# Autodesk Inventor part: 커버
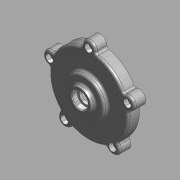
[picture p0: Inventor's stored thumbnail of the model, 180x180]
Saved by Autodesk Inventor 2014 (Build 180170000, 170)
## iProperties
Created: 2015-11
Part Number: 커버
Document SubType Name: 모델링
Designer: mdu
Material: 알루미늄 6061
Density: 2.71 g/cm^3
Appearance: 알루미늄 캐스트
Mass: 201.189 g
Surface Area: 286.328 cm^2
Volume: 74.2394 cm^3
변환 표준: STEP AP214IS
파일 이름: C:\Users\SeoGD\Desktop\?쒗뿕\而ㅻ쾭-1.stp
전처리기: Build: 253, Release: 2010 SP1 - Date: Wed 07/29/2009
전송 단위: 밀리미터
불확실성: 0.01
Author: mdu
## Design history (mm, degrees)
sketch "스케치1"
  geometry: L1 (0, 0)-(0, 26); L2 (50, 0)-(50, 15); L3 (50, 15)-(25, 15); L4 (25, 15)-(25, 21); L5 (25, 21)-(15, 21); L6 (15, 21)-(13.66, 26); L7 (13.66, 26)-(10, 26); L8 (50, 0)-(45, 0); L9 (45, 0)-(45, 10); L10 (45, 10)-(14.5, 10); L11 (14.5, 10)-(13.266, 3); L12 (13.266, 3)-(11, 3); L13 (11, 3)-(11, 16); L14 (11, 16)-(7.5, 16); L15 (7.5, 16)-(7.5, 19); L16 (7.5, 19)-(10, 19); L17 (10, 19)-(10, 26)
  constraints: 34 end point, 10 parallel, 2 perpendicular, 2 point on line, 1 vertical
  dimensions: "d11" = 100 diameter of L2 L1; "d12" = 22 diameter of L13 L1; "d13" = 90 diameter of L9 L1; "d14" = 15 distance between parallel lines of L3 L8; "d15" = 10 distance between parallel lines of L8 L10; "d16" = 29 diameter of L10.end L1; "d17" = 100 deg angle of L11 L10; "d18" = 7 distance between parallel lines of L12 L10; "d19" = 13 distance between parallel lines of L14 L12; "d20" = 3 distance between parallel lines of L16 L14; "d21" = 15 diameter of L15 L1; "d22" = 20 diameter of L17 L1; "d23" = 30 diameter of L5.end L1; "d24" = 6 distance between parallel lines of L5 L3; "d25" = 50 diameter of L4 L1; "d26" = 105 deg angle of L5 L6; "d50" = 26 distance of L1.start L1.end
revolve "회전1" sketch "스케치1" stored, may be unused: angle "d27" = 90 deg
sketch "스케치2" dims "d29" = 104
  geometry: A1 r 8.5 centre (0, 52) between (8.074, 49.344) and (-8.074, 49.344); A2 r 50 centre (0, 0) between (-8.074, 49.344) and (8.074, 49.344) reference; 2 further points
  constraints: 4 point on circle, 2 vertical alignment, 1 centre point, 1 coincident, 2 other
  dimensions: "d28" = 17 diameter of A1
extrude "돌출1" join sketch "스케치2" stored distance "d30" = 10; taper "d31" = 0 deg
fillet "모깎기3" dims "d32" = 3
fillet "모깎기4" dims "d45" = 3, "d46" = 0.2
chamfer "모따기1" distance "d47" = 1; stored, may be unused: second distance "d48" = 2, angle "d49" = 45 deg
hole "구멍2" diameter "d38" = 5.5; stored, may be unused: countersink angle "d42" = 90 deg, drill point angle "d44" = 118 deg; dims "d36" = 10, "d37" = 10, "d39" = 6, "d40" = 9.5, "d41" = 5.4, "d43" = 8
node "솔리드1"
node "솔리드 본체"
node "곡면 본체"
pattern_circular "원형 패턴1" dims angle "d34" = 360 deg
pattern_circular "원형 패턴2" dims angle "d52" = 360 deg
node "솔리드2"
